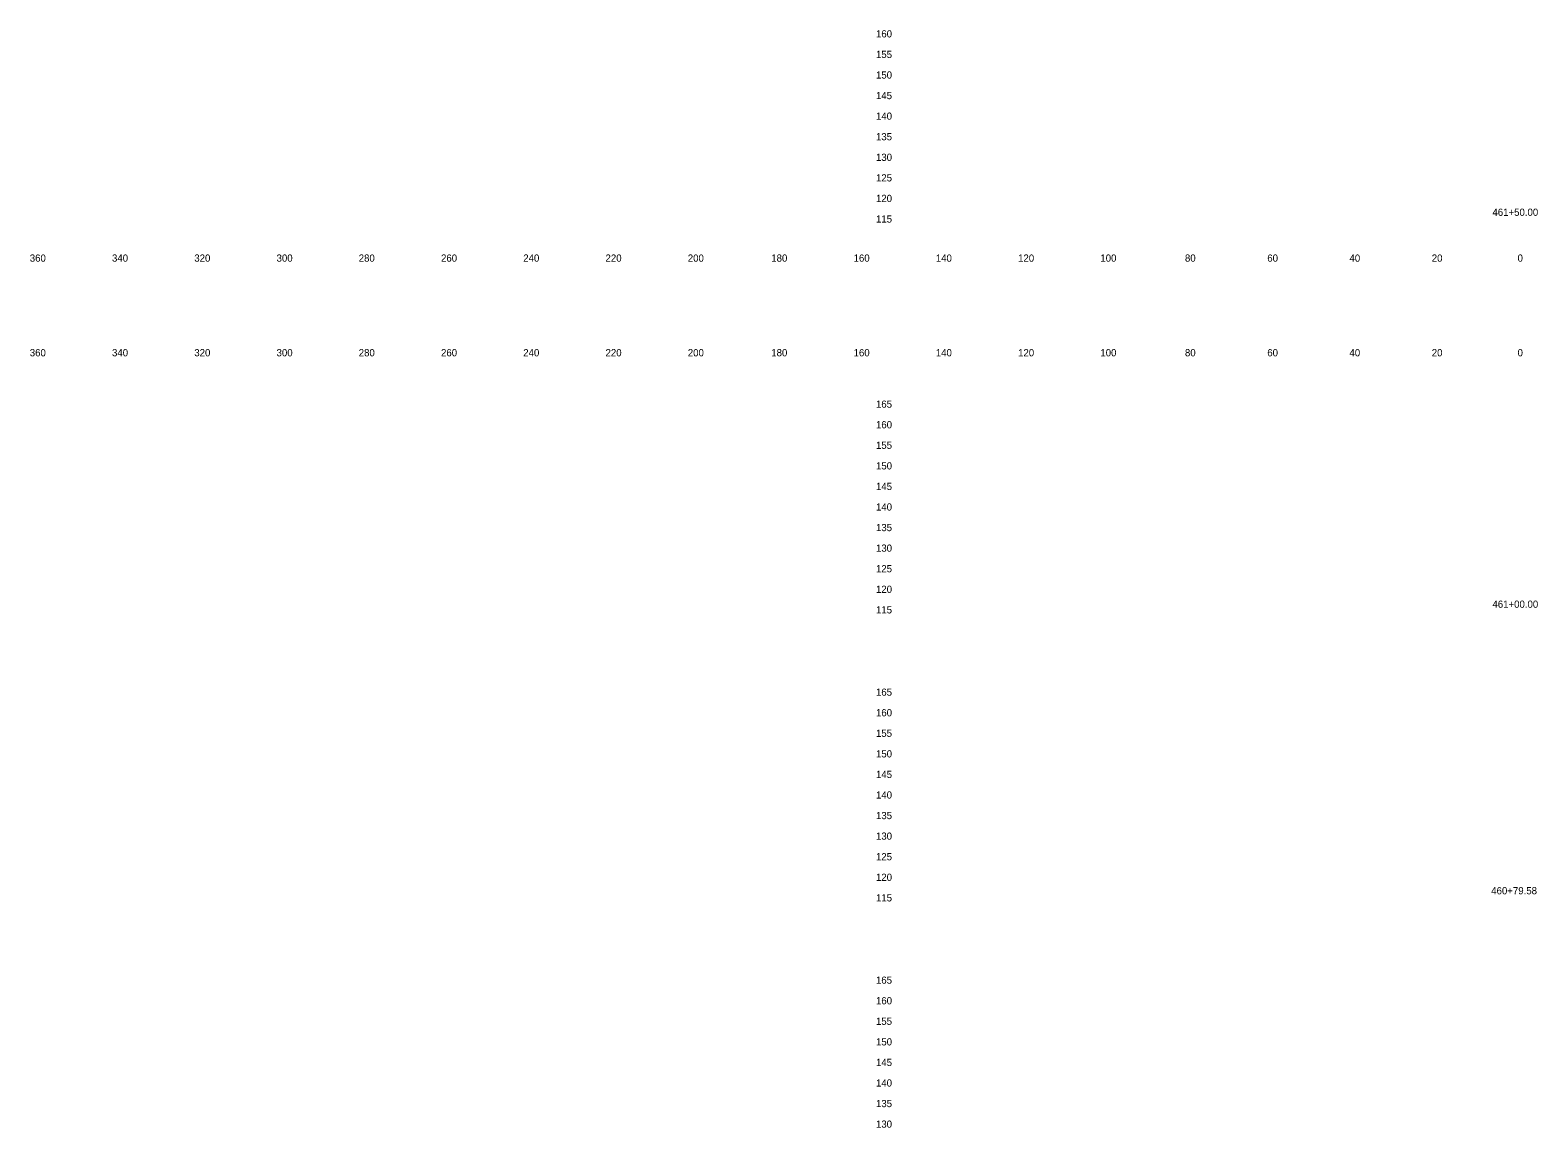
# Model space of a CAD drawing. Extents: x 21281 to 22024, y 6472 to 15198.
# Drawn here: x 21280.5 to 21647, y 8104.8 to 8371.6 of the extents above; entities that cross this region are included whole.
import ezdxf

# ---------------------------------------------------------------- set-up
doc = ezdxf.new("R2010")
doc.units = 0
for name, color, linetype in [('Draft_XS_Grid', 7, 'Continuous'), ('Draft_XS_Text', 7, 'Continuous'), ('SLOPE_STAKES_FILL', 7, 'Continuous')]:
    doc.layers.add(name, color=color, linetype=linetype)

msp = doc.modelspace()

# ---------------------------------------------------------------- texts
at = {"layer": 'Draft_XS_Grid'}
for s, p in [('  160  ', (21484.84, 8369.84)), ('  155  ', (21484.84, 8364.84)), ('  150  ', (21484.84, 8359.84)), ('  145  ', (21484.84, 8354.84)), ('  140  ', (21484.84, 8349.84)), ('  135  ', (21484.84, 8344.84)), ('  130  ', (21484.84, 8339.84)), ('  125  ', (21484.84, 8334.84)), ('  120  ', (21484.84, 8329.84)), ('  115  ', (21484.84, 8324.84)), ('  165  ', (21484.84, 8279.84)), ('  160  ', (21484.84, 8274.84)), ('  155  ', (21484.84, 8269.84)), ('  150  ', (21484.84, 8264.84)), ('  145  ', (21484.84, 8259.84)), ('  140  ', (21484.84, 8254.84)), ('  135  ', (21484.84, 8249.84)), ('  130  ', (21484.84, 8244.84)), ('  125  ', (21484.84, 8239.84)), ('  120  ', (21484.84, 8234.84)), ('  115  ', (21484.84, 8229.84)), ('  165  ', (21484.84, 8209.84)), ('  160  ', (21484.84, 8204.84)), ('  155  ', (21484.84, 8199.84)), ('  150  ', (21484.84, 8194.84)), ('  145  ', (21484.84, 8189.84)), ('  140  ', (21484.84, 8184.84)), ('  135  ', (21484.84, 8179.84)), ('  130  ', (21484.84, 8174.84)), ('  125  ', (21484.84, 8169.84)), ('  120  ', (21484.84, 8164.84)), ('  115  ', (21484.84, 8159.84)), ('  165  ', (21484.84, 8139.84)), ('  160  ', (21484.84, 8134.84)), ('  155  ', (21484.84, 8129.84)), ('  150  ', (21484.84, 8124.84)), ('  145  ', (21484.84, 8119.84)), ('  140  ', (21484.84, 8114.84)), ('  135  ', (21484.84, 8109.84)), ('  130  ', (21484.84, 8104.84))]:
    msp.add_text(s, height=1.75, dxfattribs=at).set_placement(p)
at = {"layer": 'Draft_XS_Text'}
for s, p in [('  360  ', (21279.14, 8315.34)), ('  340  ', (21299.13, 8315.34)), ('  320  ', (21319.13, 8315.34)), ('  300  ', (21339.13, 8315.34)), ('  280  ', (21359.1, 8315.34)), ('  260  ', (21379.11, 8315.34)), ('  240  ', (21399.1, 8315.34)), ('  220  ', (21419.1, 8315.34)), ('  200  ', (21439.1, 8315.34)), ('  180  ', (21459.39, 8315.34)), ('  160  ', (21479.4, 8315.34)), ('  140  ', (21499.39, 8315.34)), ('  120  ', (21519.39, 8315.34)), ('  100  ', (21539.39, 8315.34)), ('  80  ', (21559.95, 8315.34)), ('  60  ', (21579.97, 8315.34)), ('  40  ', (21599.95, 8315.34)), ('  20  ', (21619.95, 8315.34)), ('  0  ', (21640.81, 8315.34)), ('  0  ', (21640.81, 8315.34)), ('  360  ', (21279.14, 8292.34)), ('  340  ', (21299.13, 8292.34)), ('  320  ', (21319.13, 8292.34)), ('  300  ', (21339.13, 8292.34)), ('  280  ', (21359.1, 8292.34)), ('  260  ', (21379.11, 8292.34)), ('  240  ', (21399.1, 8292.34)), ('  220  ', (21419.1, 8292.34)), ('  200  ', (21439.1, 8292.34)), ('  180  ', (21459.39, 8292.34)), ('  160  ', (21479.4, 8292.34)), ('  140  ', (21499.39, 8292.34)), ('  120  ', (21519.39, 8292.34)), ('  100  ', (21539.39, 8292.34)), ('  80  ', (21559.95, 8292.34)), ('  60  ', (21579.97, 8292.34)), ('  40  ', (21599.95, 8292.34)), ('  20  ', (21619.95, 8292.34)), ('  0  ', (21640.81, 8292.34)), ('  0  ', (21640.81, 8292.34))]:
    msp.add_text(s, height=1.75, dxfattribs=at).set_placement(p)
at = {"layer": 'SLOPE_STAKES_FILL'}
for s, p in [('  461+50.00  ', (21634.7, 8326.48)), ('  461+00.00  ', (21634.7, 8231.22)), ('  460+79.58  ', (21634.41, 8161.58))]:
    msp.add_text(s, height=1.75, dxfattribs=at).set_placement(p)

doc.saveas('drawing.dxf')
